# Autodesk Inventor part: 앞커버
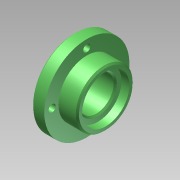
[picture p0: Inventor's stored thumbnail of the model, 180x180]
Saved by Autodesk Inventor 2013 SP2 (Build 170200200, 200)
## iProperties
Created: 2025-04
Part Number: 앞커버
Material: Generic
Document SubType Name: Modeling
Designer: i
Density: 1 g/cm^3
변환 표준: STEP AP214IS
전처리기: Build: 200, Release: 2013 SP2 Update 6 - Date: Thu 07/17/2014
전송 단위: 밀리미터
불확실성: 0.01
Author: i
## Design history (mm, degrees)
node "앞커버1"
node "솔리드1"
node "기준1"
